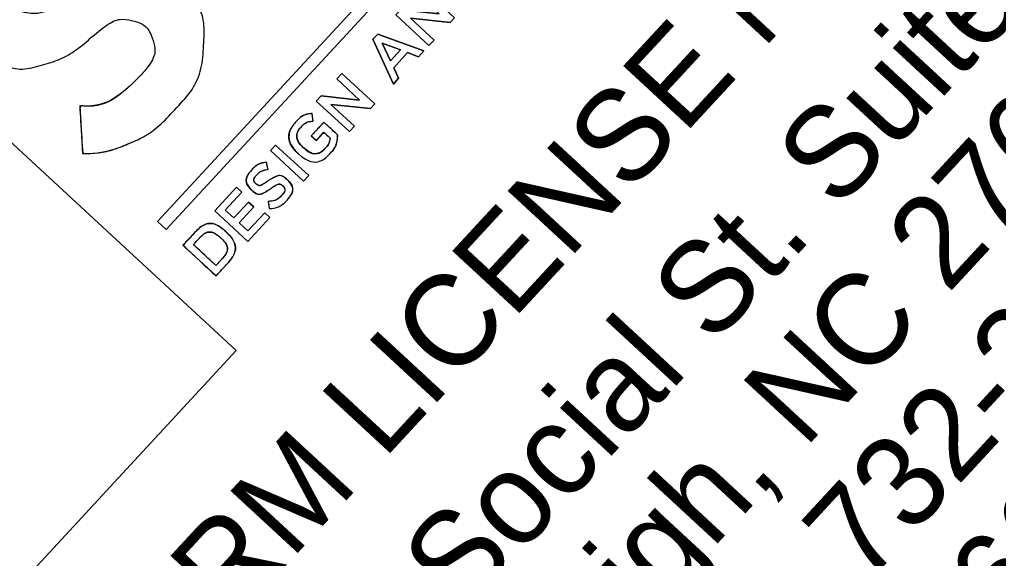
# Model space of a CAD drawing. Extents: x 1768274 to 1769121, y 999922 to 1000687.
# Drawn here: x 1768989.61 to 1768999.48, y 1000266.93 to 1000272.37 of the extents above; entities that cross this region are included whole.
import ezdxf

# ---------------------------------------------------------------- set-up
doc = ezdxf.new("R2010")
doc.units = 0
doc.layers.add('Default', color=7, linetype='Continuous')
doc.layers.add('E_NCDOT_Terrain_Model_Contour_Major', color=7, linetype='Continuous')

msp = doc.modelspace()

# ---------------------------------------------------------------- linework, layer by layer
at = {"layer": 'Default'}
msp.add_lwpolyline([(1768988.2949, 1000272.2659), (1768984.5663, 1000268.2321), (1768988.0674, 1000264.9958), (1768991.7961, 1000269.0296), (1768988.2949, 1000272.2659)], dxfattribs=at)
at = {"layer": 'E_NCDOT_Terrain_Model_Contour_Major'}
for p, q in [((1768990.2203, 1000271.4965), (1768990.2494, 1000271.0146)), ((1768992.574, 1000271.3421), (1768992.5626, 1000271.4187)), ((1768992.4782, 1000271.072), (1768992.4773, 1000271.0729)), ((1768992.4237, 1000271.0131), (1768992.4247, 1000271.0122)), ((1768992.1196, 1000270.8553), (1768992.1032, 1000270.9264)), ((1768991.9974, 1000270.7106), (1768991.9964, 1000270.7114)), ((1768992.2665, 1000270.6891), (1768992.2674, 1000270.6882)), ((1768992.3137, 1000270.7497), (1768992.3127, 1000270.7506)), ((1768991.9497, 1000270.6504), (1768991.9507, 1000270.6495)), ((1768992.1202, 1000270.5317), (1768992.1309, 1000270.4592)), ((1768991.6951, 1000270.2249), (1768991.6942, 1000270.2257)), ((1768991.6406, 1000270.1659), (1768991.6416, 1000270.165))]:
    msp.add_line(p, q, dxfattribs=at)
for points in [[(1768999.3523, 1000279.1847), (1768991.0923, 1000270.2487), (1768991.0036, 1000270.3307), (1768999.2635, 1000279.2667), (1768999.3523, 1000279.1847)], [(1768999.2635, 1000279.2667), (1768991.0036, 1000270.3307), (1768991.0923, 1000270.2487), (1768999.3523, 1000279.1847), (1768999.2635, 1000279.2667)], [(1768993.408, 1000272.4126), (1768993.4562, 1000272.4647), (1768993.8453, 1000272.4229), (1768993.6146, 1000272.6361), (1768993.6658, 1000272.6914), (1768993.9994, 1000272.3831), (1768993.9559, 1000272.336), (1768993.5554, 1000272.3789), (1768993.7928, 1000272.1595), (1768993.7416, 1000272.1042), (1768993.408, 1000272.4126)], [(1768993.7416, 1000272.1042), (1768993.7928, 1000272.1595), (1768993.5554, 1000272.3789), (1768993.9559, 1000272.336), (1768993.9994, 1000272.3831), (1768993.6658, 1000272.6914), (1768993.6146, 1000272.6361), (1768993.8453, 1000272.4229), (1768993.4562, 1000272.4647), (1768993.408, 1000272.4126), (1768993.7416, 1000272.1042)], [(1768993.1767, 1000272.1671), (1768993.2249, 1000272.2193), (1768993.691, 1000272.0495), (1768993.6361, 1000271.99), (1768993.5255, 1000272.032), (1768993.3857, 1000271.8807), (1768993.4358, 1000271.7734), (1768993.3826, 1000271.7158), (1768993.1767, 1000272.1671)], [(1768993.3826, 1000271.7158), (1768993.4358, 1000271.7734), (1768993.3857, 1000271.8807), (1768993.5255, 1000272.032), (1768993.6361, 1000271.99), (1768993.691, 1000272.0495), (1768993.2249, 1000272.2193), (1768993.1767, 1000272.1671), (1768993.3826, 1000271.7158)], [(1768993.4546, 1000272.0595), (1768993.27, 1000272.1275), (1768993.3528, 1000271.9493), (1768993.4546, 1000272.0595)], [(1768993.3528, 1000271.9493), (1768993.27, 1000272.1275), (1768993.4546, 1000272.0595), (1768993.3528, 1000271.9493)], [(1768992.6054, 1000271.5443), (1768992.6536, 1000271.5964), (1768993.0427, 1000271.5546), (1768992.812, 1000271.7678), (1768992.8632, 1000271.8231), (1768993.1968, 1000271.5148), (1768993.1532, 1000271.4676), (1768992.7528, 1000271.5106), (1768992.9901, 1000271.2912), (1768992.939, 1000271.2359), (1768992.6054, 1000271.5443)], [(1768992.939, 1000271.2359), (1768992.9901, 1000271.2912), (1768992.7528, 1000271.5106), (1768993.1532, 1000271.4676), (1768993.1968, 1000271.5148), (1768992.8632, 1000271.8231), (1768992.812, 1000271.7678), (1768993.0427, 1000271.5546), (1768992.6536, 1000271.5964), (1768992.6054, 1000271.5443), (1768992.939, 1000271.2359)], [(1768992.821, 1000271.201), (1768992.6809, 1000271.3305), (1768992.555, 1000271.1943), (1768992.606, 1000271.1472), (1768992.6817, 1000271.229), (1768992.7441, 1000271.1713)], [(1768992.1433, 1000271.0443), (1768992.1953, 1000271.1006), (1768992.5289, 1000270.7922), (1768992.4769, 1000270.736), (1768992.1433, 1000271.0443)], [(1768992.4769, 1000270.736), (1768992.5289, 1000270.7922), (1768992.1953, 1000271.1006), (1768992.1433, 1000271.0443), (1768992.4769, 1000270.736)], [(1768991.5827, 1000270.4379), (1768991.802, 1000270.6752), (1768991.8545, 1000270.6267), (1768991.6871, 1000270.4457), (1768991.7739, 1000270.3655), (1768991.9222, 1000270.526), (1768991.9746, 1000270.4775), (1768991.8263, 1000270.317), (1768991.9159, 1000270.2342), (1768992.0853, 1000270.4175), (1768992.1377, 1000270.369), (1768991.9163, 1000270.1296), (1768991.5827, 1000270.4379)], [(1768991.9163, 1000270.1296), (1768992.1377, 1000270.369), (1768992.0853, 1000270.4175), (1768991.9159, 1000270.2342), (1768991.8263, 1000270.317), (1768991.9746, 1000270.4775), (1768991.9222, 1000270.526), (1768991.7739, 1000270.3655), (1768991.6871, 1000270.4457), (1768991.8545, 1000270.6267), (1768991.802, 1000270.6752), (1768991.5827, 1000270.4379), (1768991.9163, 1000270.1296)], [(1768991.3712, 1000270.209), (1768991.2609, 1000270.0897), (1768991.5945, 1000269.7813), (1768991.7048, 1000269.9006)], [(1768991.6514, 1000269.95), (1768991.5931, 1000269.8869), (1768991.3662, 1000270.0966), (1768991.4245, 1000270.1597)]]:
    msp.add_lwpolyline(points, dxfattribs=at)
msp.add_lwpolyline([(1768984.5663, 1000268.2321), (1768988.2949, 1000272.2659), (1768991.7961, 1000269.0296), (1768988.0674, 1000264.9958)], close=True, dxfattribs=at)
for points, degree in [([(1768989.7023, 1000273.5792), (1768989.8318, 1000273.634), (1768989.9771, 1000273.6628), (1768990.138, 1000273.6657), (1768990.138, 1000273.6657), (1768990.1669, 1000273.1839), (1768990.1669, 1000273.1839), (1768989.989, 1000273.1967), (1768989.8321, 1000273.1296), (1768989.6959, 1000272.9822), (1768989.5598, 1000272.8351), (1768989.5091, 1000272.7075), (1768989.5439, 1000272.5995), (1768989.5785, 1000272.4917), (1768989.6403, 1000272.4346), (1768989.7292, 1000272.4281), (1768989.8183, 1000272.4217), (1768989.9436, 1000272.4803), (1768990.1052, 1000272.6038), (1768990.2658, 1000272.7435), (1768990.4498, 1000272.8354), (1768990.6565, 1000272.8794), (1768990.8631, 1000272.9234), (1768991.0645, 1000272.8547), (1768991.2607, 1000272.6734), (1768991.4142, 1000272.5314), (1768991.4839, 1000272.3417), (1768991.4696, 1000272.1039), (1768991.4554, 1000271.8661), (1768991.3651, 1000271.657), (1768991.1987, 1000271.477), (1768991.0407, 1000271.3061), (1768990.8832, 1000271.1871), (1768990.7261, 1000271.1198), (1768990.569, 1000271.0526), (1768990.4101, 1000271.0176), (1768990.2494, 1000271.0146), (1768990.2494, 1000271.0146), (1768990.2203, 1000271.4965), (1768990.2203, 1000271.4965), (1768990.3983, 1000271.4837), (1768990.5865, 1000271.5676), (1768990.785, 1000271.7481), (1768990.9362, 1000271.9117), (1768990.9942, 1000272.0473), (1768990.9592, 1000272.1548), (1768990.9241, 1000272.2622), (1768990.8517, 1000272.3292), (1768990.7418, 1000272.3558), (1768990.6318, 1000272.3823), (1768990.4929, 1000272.3215), (1768990.3245, 1000272.1738), (1768990.1713, 1000272.0423), (1768989.9997, 1000271.9507), (1768989.8095, 1000271.8989), (1768989.6193, 1000271.8473), (1768989.4304, 1000271.908), (1768989.2428, 1000272.0814), (1768989.0731, 1000272.2382), (1768989.0014, 1000272.4339), (1768989.0275, 1000272.6684), (1768989.0535, 1000272.9029), (1768989.1347, 1000273.0937), (1768989.2708, 1000273.2409), (1768989.4289, 1000273.4118), (1768989.5725, 1000273.5248), (1768989.7023, 1000273.5792)], 3), ([(1768989.7023, 1000273.5792), (1768989.5725, 1000273.5248), (1768989.4289, 1000273.4118), (1768989.2708, 1000273.2409), (1768989.1347, 1000273.0937), (1768989.0535, 1000272.9029), (1768989.0275, 1000272.6684), (1768989.0014, 1000272.4339), (1768989.0731, 1000272.2382), (1768989.2428, 1000272.0814), (1768989.4304, 1000271.908), (1768989.6193, 1000271.8473), (1768989.8095, 1000271.8989), (1768989.9997, 1000271.9507), (1768990.1713, 1000272.0423), (1768990.3245, 1000272.1738), (1768990.4929, 1000272.3215), (1768990.6318, 1000272.3823), (1768990.7418, 1000272.3558), (1768990.8517, 1000272.3292), (1768990.9241, 1000272.2622), (1768990.9592, 1000272.1548), (1768990.9942, 1000272.0473), (1768990.9362, 1000271.9117), (1768990.785, 1000271.7481), (1768990.5865, 1000271.5676), (1768990.3983, 1000271.4837), (1768990.2203, 1000271.4965)], 3), ([(1768990.2494, 1000271.0146), (1768990.4101, 1000271.0176), (1768990.569, 1000271.0526), (1768990.7261, 1000271.1198), (1768990.8832, 1000271.1871), (1768991.0407, 1000271.3061), (1768991.1987, 1000271.477), (1768991.3651, 1000271.657), (1768991.4554, 1000271.8661), (1768991.4696, 1000272.1039), (1768991.4839, 1000272.3417), (1768991.4142, 1000272.5314), (1768991.2607, 1000272.6734), (1768991.0645, 1000272.8547), (1768990.8631, 1000272.9234), (1768990.6565, 1000272.8794), (1768990.4498, 1000272.8354), (1768990.2658, 1000272.7435), (1768990.1052, 1000272.6038), (1768989.9436, 1000272.4803), (1768989.8183, 1000272.4217), (1768989.7292, 1000272.4281), (1768989.6403, 1000272.4346), (1768989.5785, 1000272.4917), (1768989.5439, 1000272.5995), (1768989.5091, 1000272.7075), (1768989.5598, 1000272.8351), (1768989.6959, 1000272.9822), (1768989.8321, 1000273.1296), (1768989.989, 1000273.1967), (1768990.1669, 1000273.1839)], 3), ([(1768992.4247, 1000271.0122), (1768992.4247, 1000271.0122), (1768992.4237, 1000271.0131), (1768992.4237, 1000271.0131), (1768992.3303, 1000271.0994), (1768992.3146, 1000271.2411), (1768992.4037, 1000271.3375), (1768992.4553, 1000271.3933), (1768992.5032, 1000271.4126), (1768992.5626, 1000271.4187), (1768992.5626, 1000271.4187), (1768992.574, 1000271.3421), (1768992.574, 1000271.3421), (1768992.5293, 1000271.3376), (1768992.4931, 1000271.3262), (1768992.4555, 1000271.2855), (1768992.401, 1000271.2265), (1768992.4134, 1000271.1319), (1768992.4773, 1000271.0729), (1768992.4773, 1000271.0729), (1768992.4782, 1000271.072), (1768992.4782, 1000271.072), (1768992.5468, 1000271.0086), (1768992.6375, 1000271.0054), (1768992.6979, 1000271.0707), (1768992.7258, 1000271.1009), (1768992.7411, 1000271.1375), (1768992.7441, 1000271.1713), (1768992.7441, 1000271.1713), (1768992.6817, 1000271.229), (1768992.6817, 1000271.229), (1768992.6817, 1000271.229), (1768992.606, 1000271.1472), (1768992.606, 1000271.1472), (1768992.606, 1000271.1472), (1768992.555, 1000271.1943), (1768992.555, 1000271.1943), (1768992.555, 1000271.1943), (1768992.6809, 1000271.3305), (1768992.6809, 1000271.3305), (1768992.6809, 1000271.3305), (1768992.821, 1000271.201), (1768992.821, 1000271.201), (1768992.82, 1000271.1435), (1768992.802, 1000271.0762), (1768992.7496, 1000271.0196), (1768992.6571, 1000270.9195), (1768992.5219, 1000270.9223), (1768992.4247, 1000271.0122)], 3), ([(1768992.5626, 1000271.4187), (1768992.5032, 1000271.4126), (1768992.4553, 1000271.3933), (1768992.4037, 1000271.3375), (1768992.3146, 1000271.2411), (1768992.3303, 1000271.0994), (1768992.4237, 1000271.0131)], 3), ([(1768992.4773, 1000271.0729), (1768992.4134, 1000271.1319), (1768992.401, 1000271.2265), (1768992.4555, 1000271.2855), (1768992.4931, 1000271.3262), (1768992.5293, 1000271.3376), (1768992.574, 1000271.3421)], 3), ([(1768992.4247, 1000271.0122), (1768992.5219, 1000270.9223), (1768992.6571, 1000270.9195), (1768992.7496, 1000271.0196), (1768992.802, 1000271.0762), (1768992.82, 1000271.1435), (1768992.821, 1000271.201)], 3), ([(1768992.7441, 1000271.1713), (1768992.7411, 1000271.1375), (1768992.7258, 1000271.1009), (1768992.6979, 1000271.0707), (1768992.6375, 1000271.0054), (1768992.5468, 1000271.0086), (1768992.4782, 1000271.072)], 3), ([(1768992.1032, 1000270.9264), (1768992.046, 1000270.9191), (1768991.9971, 1000270.8957), (1768991.9539, 1000270.8491), (1768991.8952, 1000270.7855), (1768991.8925, 1000270.7033), (1768991.9497, 1000270.6504)], 3), ([(1768992.1309, 1000270.4592), (1768992.1309, 1000270.4592), (1768992.1202, 1000270.5317), (1768992.1202, 1000270.5317), (1768992.1762, 1000270.5369), (1768992.2206, 1000270.5534), (1768992.257, 1000270.5927), (1768992.2891, 1000270.6274), (1768992.2922, 1000270.6653), (1768992.2674, 1000270.6882), (1768992.2674, 1000270.6882), (1768992.2665, 1000270.6891), (1768992.2665, 1000270.6891), (1768992.2427, 1000270.7111), (1768992.2179, 1000270.7102), (1768992.1487, 1000270.664), (1768992.0686, 1000270.6117), (1768992.0122, 1000270.5927), (1768991.9507, 1000270.6495), (1768991.9507, 1000270.6495), (1768991.9497, 1000270.6504), (1768991.9497, 1000270.6504), (1768991.8925, 1000270.7033), (1768991.8952, 1000270.7855), (1768991.9539, 1000270.8491), (1768991.9971, 1000270.8957), (1768992.046, 1000270.9191), (1768992.1032, 1000270.9264), (1768992.1032, 1000270.9264), (1768992.1196, 1000270.8553), (1768992.1196, 1000270.8553), (1768992.0706, 1000270.8472), (1768992.0321, 1000270.8294), (1768992.0051, 1000270.8001), (1768991.9746, 1000270.7672), (1768991.9745, 1000270.7317), (1768991.9964, 1000270.7114), (1768991.9964, 1000270.7114), (1768991.9974, 1000270.7106), (1768991.9974, 1000270.7106), (1768992.0231, 1000270.6868), (1768992.0481, 1000270.6908), (1768992.1204, 1000270.7384), (1768992.2, 1000270.7902), (1768992.2574, 1000270.8016), (1768992.3127, 1000270.7506), (1768992.3127, 1000270.7506), (1768992.3137, 1000270.7497), (1768992.3137, 1000270.7497), (1768992.3761, 1000270.692), (1768992.3698, 1000270.6105), (1768992.3077, 1000270.5433), (1768992.2624, 1000270.4944), (1768992.2021, 1000270.4646), (1768992.1309, 1000270.4592)], 3), ([(1768991.9964, 1000270.7114), (1768991.9745, 1000270.7317), (1768991.9746, 1000270.7672), (1768992.0051, 1000270.8001), (1768992.0321, 1000270.8294), (1768992.0706, 1000270.8472), (1768992.1196, 1000270.8553)], 3), ([(1768992.3127, 1000270.7506), (1768992.2574, 1000270.8016), (1768992.2, 1000270.7902), (1768992.1204, 1000270.7384), (1768992.0481, 1000270.6908), (1768992.0231, 1000270.6868), (1768991.9974, 1000270.7106)], 3), ([(1768991.9507, 1000270.6495), (1768992.0122, 1000270.5927), (1768992.0686, 1000270.6117), (1768992.1487, 1000270.664), (1768992.2179, 1000270.7102), (1768992.2427, 1000270.7111), (1768992.2665, 1000270.6891)], 3), ([(1768992.2674, 1000270.6882), (1768992.2922, 1000270.6653), (1768992.2891, 1000270.6274), (1768992.257, 1000270.5927), (1768992.2206, 1000270.5534), (1768992.1762, 1000270.5369), (1768992.1202, 1000270.5317)], 3), ([(1768992.1309, 1000270.4592), (1768992.2021, 1000270.4646), (1768992.2624, 1000270.4944), (1768992.3077, 1000270.5433), (1768992.3698, 1000270.6105), (1768992.3761, 1000270.692), (1768992.3137, 1000270.7497)], 3), ([(1768991.2609, 1000270.0897), (1768991.2609, 1000270.0897), (1768991.3712, 1000270.209), (1768991.3712, 1000270.209), (1768991.4641, 1000270.3096), (1768991.6003, 1000270.3125), (1768991.6942, 1000270.2257), (1768991.6942, 1000270.2257), (1768991.6951, 1000270.2249), (1768991.6951, 1000270.2249), (1768991.789, 1000270.1381), (1768991.7977, 1000270.0012), (1768991.7048, 1000269.9006), (1768991.7048, 1000269.9006), (1768991.5945, 1000269.7813), (1768991.5945, 1000269.7813), (1768991.5945, 1000269.7813), (1768991.2609, 1000270.0897), (1768991.2609, 1000270.0897)], 3), ([(1768991.6942, 1000270.2257), (1768991.6003, 1000270.3125), (1768991.4641, 1000270.3096), (1768991.3712, 1000270.209)], 2), ([(1768991.3662, 1000270.0966), (1768991.3662, 1000270.0966), (1768991.5931, 1000269.8869), (1768991.5931, 1000269.8869), (1768991.5931, 1000269.8869), (1768991.6514, 1000269.95), (1768991.6514, 1000269.95), (1768991.7135, 1000270.0172), (1768991.7069, 1000270.1047), (1768991.6416, 1000270.165), (1768991.6416, 1000270.165), (1768991.6406, 1000270.1659), (1768991.6406, 1000270.1659), (1768991.5753, 1000270.2262), (1768991.4866, 1000270.2269), (1768991.4245, 1000270.1597), (1768991.4245, 1000270.1597), (1768991.3662, 1000270.0966), (1768991.3662, 1000270.0966)], 3), ([(1768991.4245, 1000270.1597), (1768991.4866, 1000270.2269), (1768991.5753, 1000270.2262), (1768991.6406, 1000270.1659)], 2), ([(1768991.7048, 1000269.9006), (1768991.7977, 1000270.0012), (1768991.789, 1000270.1381), (1768991.6951, 1000270.2249)], 2), ([(1768991.6416, 1000270.165), (1768991.7069, 1000270.1047), (1768991.7135, 1000270.0172), (1768991.6514, 1000269.95)], 2)]:
    msp.add_open_spline(points, degree=degree, dxfattribs=at)

# ---------------------------------------------------------------- texts
for s, height, p in [('DOCUMENT NOT CONSIDERED FINAL', 0.720071, (1768981.9543, 1000270.7337)), ('UNLESS ALL SIGNATURES COMPLETED', 0.720071, (1768982.3086, 1000269.7441)), ('PLANS PREPARED BY:', 0.720008, (1768986.2217, 1000271.3048)), ('NC FIRM LICENSE No: C-5176', 0.92363, (1768989.5556, 1000263.8898)), ('1000 Social St. Suite 800', 0.92363, (1768991.9851, 1000264.0751)), ('Raleigh, NC 27609', 0.92363, (1768994.2181, 1000264.4499)), ('(919) 732-6676 (FAX)', 0.92363, (1768995.7144, 1000261.9864)), ('(919) 732-3883', 0.92363, (1768995.942, 1000264.2738))]:
    msp.add_text(s, height=height, rotation=47.25123, dxfattribs=at).set_placement(p)

doc.saveas('drawing.dxf')
